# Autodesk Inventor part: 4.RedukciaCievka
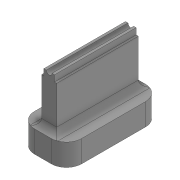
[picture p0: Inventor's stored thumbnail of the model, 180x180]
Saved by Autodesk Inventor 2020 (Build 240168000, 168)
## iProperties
Created: 2022-04
Part Number: 4.RedukciaCievka
Material: Generic
Document SubType Name: Modeling
Designer: marti
Density: 1 g/cm^3
Appearance: Default(1)
Mass: 3.58991 g
Surface Area: 19.7424 cm^2
Volume: 3.58991 cm^3
Author: marti
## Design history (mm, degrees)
sketch "Sketch1"
  geometry: L1 (7.5, -15)-(-7.5, -15); L2 (-7.5, -15)-(-7.5, 15); L3 (-7.5, 15)-(7.5, 15); L4 (7.5, 15)-(7.5, -15); L5 (7.5, -15)-(-7.5, 15); L6 (-7.5, -15)-(7.5, 15); 1 further point
  constraints: 12 end point, 2 midpoint, 2 parallel, 1 horizontal, 1 perpendicular
  dimensions: "d0" = 15 distance of L2.end L3.end; "d1" = 30 distance of L1.end L2.end
extrude "Extrusion1" new body sketch "Sketch1" distance "d2" = 7; taper "d3" = 0 deg
sketch "Sketch2"
  geometry: L1 (-7.5, 15)-(7.5, 15) reference; L2 (7.5, 15)-(7.5, -15) reference; L3 (7.5, -15)-(-7.5, -15) reference; C1 r 1.35 at (0, 10); C2 r 1.35 at (0, -10); 1 further point
  constraints: 2 centre point
  dimensions: "d4" = 2.7 diameter of C1; "d5" = 5 distance from line of C1.centre L1; "d6" = 7.5 distance from line of L2 C1.centre; "d7" = 2.7 diameter of C2 (= d4); "d8" = 5 distance from line of L3 C2.centre (= d5); "d9" = 7.5 distance from line of L2 C2.centre (= d6)
extrude "Extrusion2" cut sketch "Sketch2" distance "d10" = 6; taper "d11" = 0 deg
fillet "Fillet1" dims "d17" = 4.85
sketch "Sketch4"
  geometry: L1 (-2.4, 13)-(2.4, 13); L2 (2.4, 13)-(2.4, -13); L3 (2.4, -13)-(-2.4, -13); L4 (-2.4, -13)-(-2.4, 13); L5 (-2.4, 13)-(2.4, -13); L6 (2.4, 13)-(-2.4, -13); 1 further point
  constraints: 12 end point, 2 midpoint, 2 parallel, 1 horizontal, 1 perpendicular
  dimensions: "d19" = 4.8 distance of L2.end L3.end; "d20" = 26 distance of L1.end L2.end
extrude "Extrusion4" join sketch "Sketch4" distance "d21" = 16.1; taper "d22" = 0 deg
sketch "Sketch5"
  geometry: L1 (2.4, -13)-(2.4, 13) reference; L2 (-2.4, 13)-(2.4, 13); L3 (2.4, 13)-(2.4, -13); L4 (2.4, -13)-(-2.4, -13); L5 (-2.4, -13)-(-2.4, 13); L6 (-2.4, 13)-(2.4, -13); L7 (2.4, 13)-(-2.4, -13); L8 (-2.4, -13)-(2.4, -13) reference; L9 (-1.7, 13)-(1.7, 13); L10 (1.7, 13)-(1.7, -13); L11 (1.7, -13)-(-1.7, -13); L12 (-1.7, -13)-(-1.7, 13); L13 (-1.7, 13)-(1.7, -13); L14 (1.7, 13)-(-1.7, -13); 6 further points
  constraints: 24 end point, 4 midpoint, 4 parallel, 2 horizontal, 2 perpendicular, 1 point on line
  dimensions: "d23" = 3.4 distance of L10.end L11.end
extrude "Extrusion5" cut sketch "Sketch5" distance "d24" = 2; taper "d25" = 0 deg
fillet "Fillet2" dims "d26" = 2
sketch "Sketch7"
  geometry: L1 (0, 0)-(3.4, 0) reference; L2 (0, 0)-(0.8, 0); L3 (3.4, 0)-(2.6, 0); L4 (0.8, 0)-(2.6, 0); A1 r 0.9 centre (1.7, 0) between (0.8, 0) and (2.6, 0); 1 further point
  constraints: 6 end point, 3 point on circle, 2 point on line, 1 centre point
  dimensions: "d31" = 0.8 distance of L1.start L2.end; "d32" = 0.8 distance of L1.end L3.end; "d33" = 0.9 radius of A1
extrude "Extrusion7" cut sketch "Sketch7" distance "d34" = 26; taper "d35" = 0 deg
body "Solid1"
